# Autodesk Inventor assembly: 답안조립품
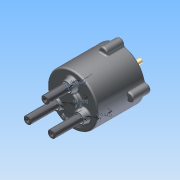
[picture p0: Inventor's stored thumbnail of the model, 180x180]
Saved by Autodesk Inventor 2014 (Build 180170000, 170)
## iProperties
Created: 2015-09
Part Number: 답안조립품
Document SubType Name: Assembly
Designer: study
Mass: 2160.25 g
Surface Area: 1801.24 cm^2
Volume: 438.523 cm^3
Density: 4.9262 g/cm^3
Author: study
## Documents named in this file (14)
- C:\Users\study\Desktop\350916V1015\답안조립품.iam
- C:\Users\study\Desktop\350916V1015\몸체.ipt
- C:\Users\study\Desktop\350916V1015\M5x0.8x20.ipt
- C:\Users\study\Desktop\350916V1015\커버.ipt
- C:\Users\study\Desktop\350916V1015\오일실.ipt
- C:\Users\study\Desktop\350916V1015\베어링 NA 4900.ipt
- C:\Users\study\Desktop\350916V1015\메인 축.ipt
- C:\Users\study\Desktop\350916V1015\멈춤링 10 x 1.ipt
- C:\Users\study\Desktop\350916V1015\멈춤링 22 x 1.2.ipt
- C:\Users\study\Desktop\350916V1015\판캠.ipt
- C:\Users\study\Desktop\350916V1015\슬라이드 축.ipt
- C:\Users\study\Desktop\350916V1015\11가변 스프링.ipt
- C:\Users\study\Desktop\350916V1015\12가변 스프링.ipt
- C:\Users\study\Desktop\350916V1015\13가변 스프링.ipt
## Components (7 placed, 4 different names)
1. 11가변 스프링:1
2. 12가변 스프링:1
3. 13가변 스프링:1
4. M5x0.8x20:1
5. M5x0.8x20:2
6. M5x0.8x20:3
7. M5x0.8x20:4
